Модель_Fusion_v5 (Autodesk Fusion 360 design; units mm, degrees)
work_plane "WorkPlane1" AlongDistance 0 ExtraOffset 0
sketch "Sketch1" plane through (0, 0, 0) normal (0, 1, 0) x axis (1, 0, 0)
  line L1 (850, -2) -> (150, -2)
  line L2 (150, -298) -> (850, -298)
  arc A1 centre (850, -150) radius 148 clockwise from (850, -2) to (850, -298)
  arc A2 centre (150, -150) radius 148 clockwise from (150, -298) to (150, -2)
extrude "Extrude1" new body sketch "Sketch1" along normal blind 16
work_plane "WorkPlane2" AlongDistance 0 ExtraOffset 0
sketch "Sketch2" plane through (0, 0, 0) normal (0, 1, 0) x axis (1, 0, 0)
  line L1 (208.1, -37) -> (208.1, 3)
  line L2 (191.9, -37) -> (208.1, -37)
  line L3 (191.9, 3) -> (191.9, -37)
  line L4 (208.1, 3) -> (191.9, 3)
  line L5 (408.1, -37) -> (408.1, 3)
  line L6 (391.9, -37) -> (408.1, -37)
  line L7 (391.9, 3) -> (391.9, -37)
  line L8 (408.1, 3) -> (391.9, 3)
  line L9 (499.1, -37) -> (499.1, 3)
  line L10 (482.9, -37) -> (499.1, -37)
  line L11 (482.9, 3) -> (482.9, -37)
  line L12 (499.1, 3) -> (482.9, 3)
  line L13 (517.1, -37) -> (517.1, 3)
  line L14 (500.9, -37) -> (517.1, -37)
  line L15 (500.9, 3) -> (500.9, -37)
  line L16 (517.1, 3) -> (500.9, 3)
  line L17 (608.1, -37) -> (608.1, 3)
  line L18 (591.9, -37) -> (608.1, -37)
  line L19 (591.9, 3) -> (591.9, -37)
  line L20 (608.1, 3) -> (591.9, 3)
  line L21 (808.1, -37) -> (808.1, 3)
  line L22 (791.9, -37) -> (808.1, -37)
  line L23 (791.9, 3) -> (791.9, -37)
  line L24 (808.1, 3) -> (791.9, 3)
  line L25 (191.9, -263) -> (191.9, -303)
  line L26 (208.1, -263) -> (191.9, -263)
  line L27 (208.1, -303) -> (208.1, -263)
  line L28 (191.9, -303) -> (208.1, -303)
  line L29 (391.9, -263) -> (391.9, -303)
  line L30 (408.1, -263) -> (391.9, -263)
  line L31 (408.1, -303) -> (408.1, -263)
  line L32 (391.9, -303) -> (408.1, -303)
  line L33 (482.9, -263) -> (482.9, -303)
  line L34 (499.1, -263) -> (482.9, -263)
  line L35 (499.1, -303) -> (499.1, -263)
  line L36 (482.9, -303) -> (499.1, -303)
  line L37 (500.9, -263) -> (500.9, -303)
  line L38 (517.1, -263) -> (500.9, -263)
  line L39 (517.1, -303) -> (517.1, -263)
  line L40 (500.9, -303) -> (517.1, -303)
  line L41 (591.9, -263) -> (591.9, -303)
  line L42 (608.1, -263) -> (591.9, -263)
  line L43 (608.1, -303) -> (608.1, -263)
  line L44 (591.9, -303) -> (608.1, -303)
  line L45 (791.9, -263) -> (791.9, -303)
  line L46 (808.1, -263) -> (791.9, -263)
  line L47 (808.1, -303) -> (808.1, -263)
  line L48 (791.9, -303) -> (808.1, -303)
  line L49 (913.5148, -56.1891) -> (933.5148, -21.5481)
  line L50 (899.4852, -48.0891) -> (913.5148, -56.1891)
  line L51 (919.4852, -13.4481) -> (899.4852, -48.0891)
  line L52 (933.5148, -21.5481) -> (919.4852, -13.4481)
  line L53 (963, -158.1) -> (1003, -158.1)
  line L54 (963, -141.9) -> (963, -158.1)
  line L55 (1003, -141.9) -> (963, -141.9)
  line L56 (1003, -158.1) -> (1003, -141.9)
  line L57 (899.4852, -251.9109) -> (919.4852, -286.5519)
  line L58 (913.5148, -243.8109) -> (899.4852, -251.9109)
  line L59 (933.5148, -278.4519) -> (913.5148, -243.8109)
  line L60 (919.4852, -286.5519) -> (933.5148, -278.4519)
  line L61 (86.4852, -243.8109) -> (66.4852, -278.4519)
  line L62 (100.5148, -251.9109) -> (86.4852, -243.8109)
  line L63 (80.5148, -286.5519) -> (100.5148, -251.9109)
  line L64 (66.4852, -278.4519) -> (80.5148, -286.5519)
  line L65 (37, -141.9) -> (-3, -141.9)
  line L66 (37, -158.1) -> (37, -141.9)
  line L67 (-3, -158.1) -> (37, -158.1)
  line L68 (-3, -141.9) -> (-3, -158.1)
  line L69 (100.5148, -48.0891) -> (80.5148, -13.4481)
  line L70 (86.4852, -56.1891) -> (100.5148, -48.0891)
  line L71 (66.4852, -21.5481) -> (86.4852, -56.1891)
  line L72 (80.5148, -13.4481) -> (66.4852, -21.5481)
extrude "Extrude2" cut sketch "Sketch2" profile of L1 L2 L3 L4 L21 L22 L23 L24 L25 L26 L27 L28 L45 L46 L47 L48 L49 L50 L51 L52 L53 L54 L55 L56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 along normal blind 16
work_plane "WorkPlane3" AlongDistance 0 ExtraOffset 0
sketch "Sketch3" plane through (0, 0, 0) normal (0, 1, 0) x axis (1, 0, 0)
  circle C1 centre (206.9686, -35.8686) radius 1.6
  circle C2 centre (193.0314, -35.8686) radius 1.6
  circle C3 centre (406.9686, -35.8686) radius 1.6
  circle C4 centre (393.0314, -35.8686) radius 1.6
  circle C5 centre (497.9686, -35.8686) radius 1.6
  circle C6 centre (484.0314, -35.8686) radius 1.6
  circle C7 centre (515.9686, -35.8686) radius 1.6
  circle C8 centre (502.0314, -35.8686) radius 1.6
  circle C9 centre (606.9686, -35.8686) radius 1.6
  circle C10 centre (593.0314, -35.8686) radius 1.6
  circle C11 centre (806.9686, -35.8686) radius 1.6
  circle C12 centre (793.0314, -35.8686) radius 1.6
  circle C13 centre (193.0314, -264.1314) radius 1.6
  circle C14 centre (206.9686, -264.1314) radius 1.6
  circle C15 centre (393.0314, -264.1314) radius 1.6
  circle C16 centre (406.9686, -264.1314) radius 1.6
  circle C17 centre (484.0314, -264.1314) radius 1.6
  circle C18 centre (497.9686, -264.1314) radius 1.6
  circle C19 centre (502.0314, -264.1314) radius 1.6
  circle C20 centre (515.9686, -264.1314) radius 1.6
  circle C21 centre (593.0314, -264.1314) radius 1.6
  circle C22 centre (606.9686, -264.1314) radius 1.6
  circle C23 centre (793.0314, -264.1314) radius 1.6
  circle C24 centre (806.9686, -264.1314) radius 1.6
  circle C25 centre (913.1007, -54.6436) radius 1.6
  circle C26 centre (901.0307, -47.675) radius 1.6
  circle C27 centre (964.1314, -156.9686) radius 1.6
  circle C28 centre (964.1314, -143.0314) radius 1.6
  circle C29 centre (901.0307, -252.325) radius 1.6
  circle C30 centre (913.1007, -245.3564) radius 1.6
  circle C31 centre (86.8993, -245.3564) radius 1.6
  circle C32 centre (98.9693, -252.325) radius 1.6
  circle C33 centre (35.8686, -143.0314) radius 1.6
  circle C34 centre (35.8686, -156.9686) radius 1.6
  circle C35 centre (98.9693, -47.675) radius 1.6
  circle C36 centre (86.8993, -54.6436) radius 1.6
extrude "Extrude3" cut sketch "Sketch3" profile of C1 C2 C11 C12 C13 C14 C23 C24 C25 C26 C27 C28 C29 C30 C31 C32 C33 C34 C35 C36 along normal blind 16
copy_paste "CopyPaste1"
work_plane "WorkPlane1" AlongDistance 982 ExtraOffset 0
sketch "Sketch1" plane through (0, 982, 0) normal (0, 1, 0) x axis (1, 0, 0)
  line L1 (850, -2) -> (150, -2)
  line L2 (150, -298) -> (850, -298)
  line L3 (850, -30) -> (150, -30)
  line L4 (150, -270) -> (850, -270)
  arc A1 centre (850, -150) radius 148 clockwise from (850, -2) to (850, -298)
  arc A2 centre (150, -150) radius 148 clockwise from (150, -298) to (150, -2)
  arc A3 centre (850, -150) radius 120 clockwise from (850, -30) to (850, -270)
  arc A4 centre (150, -150) radius 120 clockwise from (150, -270) to (150, -30)
extrude "Extrude1" new body sketch "Sketch1" along normal blind 16
work_plane "WorkPlane1" AlongDistance 850 ExtraOffset 0
sketch "Sketch1" plane through (0, 850, 0) normal (0, 1, 0) x axis (1, 0, 0)
  line L1 (850, -30) -> (150, -30)
  line L2 (150, -270) -> (850, -270)
  arc A1 centre (850, -150) radius 120 clockwise from (850, -30) to (850, -270)
  arc A2 centre (150, -150) radius 120 clockwise from (150, -270) to (150, -30)
extrude "Extrude1" new body sketch "Sketch1" along normal blind 16
work_plane "WorkPlane1" AlongDistance -8 ExtraOffset 0
sketch "Sketch1" plane through (0, 0, -8) normal (0, 0, 1) x axis (1, 0, 0)
  line L1 (35, 0) -> (0, 0)
  line L2 (35, 16.1) -> (35, 0)
  line L3 (70, 16.1) -> (35, 16.1)
  line L4 (70, 490.9) -> (70, 16.1)
  line L5 (35, 490.9) -> (70, 490.9)
  line L6 (35, 507.1) -> (35, 490.9)
  line L7 (70, 507.1) -> (35, 507.1)
  line L8 (70, 850) -> (70, 507.1)
  line L9 (28, 850) -> (70, 850)
  line L10 (28, 982) -> (28, 850)
  line L11 (0, 982) -> (28, 982)
  line L12 (0, 0) -> (0, 982)
extrude "Extrude1" new body sketch "Sketch1" along a picked direction blind 16
work_plane "WorkPlane2" AlongDistance -8 ExtraOffset 0
sketch "Sketch2" plane through (0, 0, -8) normal (0, 0, 1) x axis (1, 0, 0)
  circle C1 centre (36.1314, 14.9686) radius 1.6
  circle C2 centre (36.1314, 492.0314) radius 1.6
  circle C3 centre (36.1314, 505.9686) radius 1.6
extrude "Extrude4" cut sketch "Sketch2" along a picked direction blind 16
copy_paste "CopyPaste2"
copy_paste "CopyPaste3"
copy_paste "CopyPaste4"
copy_paste "CopyPaste5"
copy_paste "CopyPaste6"
copy_paste "CopyPaste7"
copy_paste "CopyPaste8"
copy_paste "CopyPaste9"
copy_paste "CopyPaste10"
copy_paste "CopyPaste11"
copy_paste "CopyPaste12"
work_plane "WorkPlane1" AlongDistance -8 ExtraOffset 0
sketch "Sketch1" plane through (0, 0, -8) normal (0, 0, 1) x axis (1, 0, 0)
  line L1 (35, 0) -> (0, 0)
  line L2 (35, 16.1) -> (35, 0)
  line L3 (70, 16.1) -> (35, 16.1)
  line L4 (70, 490.9) -> (70, 16.1)
  line L5 (35, 490.9) -> (70, 490.9)
  line L6 (35, 507.1) -> (35, 490.9)
  line L7 (70, 507.1) -> (35, 507.1)
  line L8 (70, 850) -> (70, 507.1)
  line L9 (28, 850) -> (70, 850)
  line L10 (28, 982) -> (28, 850)
  line L11 (0, 982) -> (28, 982)
  line L12 (0, 0) -> (0, 982)
extrude "Extrude1" new body sketch "Sketch1" along a picked direction blind 16
work_plane "WorkPlane2" AlongDistance -8 ExtraOffset 0
sketch "Sketch2" plane through (0, 0, -8) normal (0, 0, 1) x axis (1, 0, 0)
  circle C1 centre (36.1314, 14.9686) radius 1.6
  circle C2 centre (36.1314, 492.0314) radius 1.6
  circle C3 centre (36.1314, 505.9686) radius 1.6
extrude "Extrude5" cut sketch "Sketch2" along a picked direction blind 16
work_plane "WorkPlane3" AlongDistance 0 ExtraOffset 0
sketch "Sketch3" plane through (0, 0, 0) normal (0, 1, 0) x axis (1, 0, 0)
  line L1 (0.2164, 8) -> (-10, 8)
  line L2 (-10, -8) -> (0.2164, -8)
  line L3 (-10, 8) -> (-10, -8)
  arc A1 centre (148, 0) radius 148 clockwise from (0.2164, -8) to (0.2164, 8)
extrude "Extrude3" cut sketch "Sketch3" along normal blind 982
copy_paste "CopyPaste13"
copy_paste "CopyPaste14"
copy_paste "CopyPaste15"
copy_paste "CopyPaste16"
copy_paste "CopyPaste17"
work_plane "WorkPlane1" AlongDistance 0 ExtraOffset 0
sketch "Sketch1" plane through (0, 0, 0) normal (0, 1, 0) x axis (1, 0, 0)
  line L1 (850, 0) -> (150, 0)
  line L2 (150, -300) -> (850, -300)
  line L3 (850, -2) -> (150, -2)
  line L4 (150, -298) -> (850, -298)
  arc A1 centre (850, -150) radius 150 clockwise from (850, 0) to (850, -300)
  arc A2 centre (150, -150) radius 150 clockwise from (150, -300) to (150, 0)
  arc A3 centre (850, -150) radius 148 clockwise from (850, -2) to (850, -298)
  arc A4 centre (150, -150) radius 148 clockwise from (150, -298) to (150, -2)
extrude "Extrude1" new body sketch "Sketch1" along normal blind 998
work_plane "WorkPlane2" AlongDistance 500 ExtraOffset 0
split "Split1"
work_plane "WorkPlane1" AlongDistance 866 ExtraOffset 0
sketch "Sketch1" plane through (0, 866, 0) normal (0, 1, 0) x axis (1, 0, 0)
  line L1 (850, -30) -> (150, -30)
  line L2 (150, -270) -> (850, -270)
  line L3 (850, -32) -> (150, -32)
  line L4 (150, -268) -> (850, -268)
  arc A1 centre (850, -150) radius 120 clockwise from (850, -30) to (850, -270)
  arc A2 centre (150, -150) radius 120 clockwise from (150, -270) to (150, -30)
  arc A3 centre (850, -150) radius 118 clockwise from (850, -32) to (850, -268)
  arc A4 centre (150, -150) radius 118 clockwise from (150, -268) to (150, -32)
extrude "Extrude1" new body sketch "Sketch1" along normal blind 132
work_plane "WorkPlane2" AlongDistance 500 ExtraOffset 0
split "Split1"
work_plane "WorkPlane1" AlongDistance 998 ExtraOffset 0
sketch "Sketch1" plane through (0, 998, 0) normal (0, 1, 0) x axis (1, 0, 0)
  line L1 (850, 0) -> (150, 0)
  line L2 (150, -300) -> (850, -300)
  line L3 (850, -32) -> (150, -32)
  line L4 (150, -268) -> (850, -268)
  arc A1 centre (850, -150) radius 150 clockwise from (850, 0) to (850, -300)
  arc A2 centre (150, -150) radius 150 clockwise from (150, -300) to (150, 0)
  arc A3 centre (850, -150) radius 118 clockwise from (850, -32) to (850, -268)
  arc A4 centre (150, -150) radius 118 clockwise from (150, -268) to (150, -32)
extrude "Extrude1" new body sketch "Sketch1" along normal blind 2
remove_instance "RemoveInstance1"
remove_instance "RemoveInstance2"
remove_instance "RemoveInstance3"
remove_instance "RemoveInstance4"
work_plane "WorkPlane4" AlongDistance 0 ExtraOffset 0
sketch "Sketch4" plane through (0, 0, 0) normal (0, 1, 0) x axis (1, 0, 0)
  line L1 (516.1, 3) -> (483.9, 3)
  line L2 (516.1, -37) -> (516.1, 3)
  line L3 (483.9, -37) -> (516.1, -37)
  line L4 (483.9, 3) -> (483.9, -37)
  line L5 (516.1, -303) -> (483.9, -303)
  line L6 (516.1, -263) -> (516.1, -303)
  line L7 (483.9, -263) -> (516.1, -263)
  line L8 (483.9, -303) -> (483.9, -263)
extrude "Extrude6" cut sketch "Sketch4" along normal blind 16
work_plane "WorkPlane5" AlongDistance 0 ExtraOffset 0
sketch "Sketch5" plane through (0, 0, 0) normal (0, 1, 0) x axis (1, 0, 0)
  circle C1 centre (485.0314, -35.8686) radius 1.6
  circle C2 centre (514.9686, -35.8686) radius 1.6
  circle C3 centre (485.0314, -264.1314) radius 1.6
  circle C4 centre (514.9686, -264.1314) radius 1.6
extrude "Extrude7" cut sketch "Sketch5" along normal blind 16
position "Position1"
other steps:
extrude "Extrude2" cut sketch "Sketch2" along a picked direction blind 16
extrude "Extrude2" cut sketch "Sketch2" along a picked direction blind 16
create_component "CreateComponent1"
create_component "CreateComponent1"
create_component "CreateComponent2"
create_component "CreateComponent3"
create_component "CreateComponent4"
create_component "CreateComponent5"
create_component "CreateComponent6"
create_component "CreateComponent7"
create_component "CreateComponent8"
